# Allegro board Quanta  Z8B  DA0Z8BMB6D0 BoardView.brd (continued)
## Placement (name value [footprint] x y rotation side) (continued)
PC46  0.1u/50v_6  [CC0603]  39.43 65.7 90 top
PC47  0.1u/50v_6  [CC0603]  41.76 69.46 90 top
PC48  0.1u/50v_6  [CC0603]  39.2 71.49 180 top
PC49  *2.2n/50v_4  [CC0402]  123.26 11.11 0 bottom
PC50  2200p/50v_6  [CC0603]  197.11 130.14 0 top
PC51  4.7u/25v_8  [CC0805]  196.72 128.39 180 top
PC52  1u/10v_4  [CC0402]  186.59 124.94 270 bottom
PC53  0.1u/50v_6  [CC0603]  192.03 126.84 0 bottom
PC54  0.1u/50v_6  [CC0603]  179.99 124.07 0 top
PC55  330u/2.5v_6x4.2  [ECAP6_3X6_1-7_2]  180.44 121.86 90 bottom
PC56  2200p/50v_6  [CC0603]  180.85 127.07 90 top
PC57  10u/6.3v_6  [CC0603]  54.46 27.3 0 bottom
PC58  10u/6.3v_6  [CC0603]  54.48 25.98 0 bottom
PC59  0.22u/10v_4  [CC0402]  49.96 29.1 180 top
PC60  10u/6.3v_6  [CC0603]  54.48 27.3 180 top
PC61  1u/10v_4  [CC0402]  53.06 33.62 180 bottom
PC62  2200p/50v_4  [CC0402]  51.39 41.7 270 top
PC63  4.7u/25v_8  [CC0805]  50.3 40.18 90 bottom
PC64  0.1u/50v_6  [CC0603]  56.29 33.72 0 top
PC65  0.1u/50v_6  [CC0603]  61.04 28.8 180 bottom
PC66  330u/2.5v_6x4.2  [ECAP6_3X6_1-7_2]  62.23 33.09 270 bottom
PC67  *680p/50v_6  [CC0603]  57.81 39.44 90 top
PC68  0.1u/10v_4  [CC0402]  49.96 30.27 180 top
PC69  0.01u/25v_4  [CC0402]  49.96 32.61 180 top
PC70  1u/10v_4  [CC0402]  57.18 85.72 270 bottom
PC71  0.1u/50v_6  [CC0603]  53.04 78.15 0 top
PC72  2200p/50v_4  [CC0402]  52.76 78.22 0 bottom
PC73  10u/25v_8  [CC0805]  53.42 79.88 0 top
PC74  10u/25v_8  [CC0805]  53.44 79.9 0 bottom
PC75  33u/25v_6x4.5  [ECAP6_3X6_1-7_2]  47.53 79.14 0 bottom
PC76  ev@2200p/50v_6  [CC0603]  133.25 190.24 90 top
PC77  0.47u/10v_4  [CC0402]  42.68 99 0 bottom
PC78  1n/50v_4  [CC0402]  42.8 89.78 270 top
PC79  2.2u/10v_6  [CC0603]  44.15 95.24 90 top
PC80  0.1u/10v_4  [CC0402]  100.22 122.33 0 top
PC82  22u/6.3v_8  [CC0805]  73.05 84.78 0 top
PC83  22u/6.3v_8  [CC0805]  73.05 86.94 0 top
PC84  0.22u/25v_6  [CC0603]  51.49 86.05 180 top
PC85  3300p/50v_6  [CC0603]  56.52 77.01 0 bottom
PC86  *0.1u/25v_4  [CC0402]  39.2 89.35 0 bottom
PC87  0.15u/10v_4  [CC0402]  40.87 90.04 270 bottom
PC88  0.1u/10v_4  [CC0402]  47.38 99.23 0 top
PC89  *0.1u/25v_4  [CC0402]  39.2 90.52 0 bottom
PC90  *100p/50v_4  [CC0402]  40.9 97.83 270 bottom
PC91  *330p/50v_4  [CC0402]  37.34 97.45 0 bottom
PC92  4700p/25v_4  [CC0402]  43.95 89.78 270 top
PC93  330p/50v_4  [CC0402]  39.76 97.83 270 bottom
PC94  *0.01u/50v_4  [CC0402]  37.37 94.86 0 bottom
PC95  10u/6.3v_6  [CC0603]  163.84 142.85 180 bottom
PC96  0.1u/25v_6  [CC0603]  163.84 144.12 0 bottom
PC97  0.1u/50v_6  [CC0603]  160.89 136.16 180 bottom
PC98  0.1u/10v_4  [CC0402]  153.57 134.44 180 bottom
PC99  10u/6.3v_6  [CC0603]  153.32 131.64 0 bottom
PC100  10u/6.3v_6  [CC0603]  153.32 133.04 0 bottom
PC101  1000p/50v_4  [CC0402]  158.04 140.51 180 bottom
PC102  *100p/50v_4  [CC0402]  167.31 138.35 0 bottom
PC103  1500p/50v_4  [CC0402]  167.31 139.44 180 bottom
PC104  0.01u/25v_4  [CC0402]  165.61 136 180 bottom
PC105  *2200p/50v_4  [CC0402]  30.38 50.49 270 top
PC106  0.1u/50v_6  [CC0603]  52.99 105.35 270 top
PC107  0.1u/50v_6  [CC0603]  54.38 105.35 270 top
PC108  ev@0.1u/50v_6  [CC0603]  191.44 146.17 90 top
PC109  ev@4.7u/25v_8  [CC0805]  179.51 146.27 270 top
PC110  ev@4.7u/25v_8  [CC0805]  187.56 146.5 270 top
PC111  ev@33u/25v_6x4.5  [ECAP6_3X6_1-7_2]  183.42 150.31 180 bottom
PC112  ev@1u/10v_4  [CC0402]  184.94 143.71 180 bottom
PC113  *ev@0.01u/25v_4  [CC0402]  179.17 134.31 180 top
PC114  ev@0.22u/25v_6  [CC0603]  188.34 141.55 0 top
PC115  ev@2200p/50v_4  [CC0402]  174.22 146.37 270 top
PC116  ev@0.1u/10v_4  [CC0402]  172.87 167.33 0 bottom
PC117  ev@10u/6.3v_8  [CC0805]  178.34 170.5 270 bottom
PC118  ev@330u/2v_7343  [CC7343]  185.75 162.07 270 top
PC119  ev@1u/10v_4  [CC0402]  183.16 135.58 270 bottom
PC120  ev@1000p/50v_6  [CC0603]  188.75 158.72 90 top
PC121  *e@0.01u/25v_4  [CC0402]  184.3 135.58 270 bottom
PC122  ev@5600p/25v_4  [CC0402]  186.59 135.58 90 bottom
PC123  ev@4700p/25v_4  [CC0402]  179.48 139.01 0 top
PC124  ev@22p/50v_4  [CC0402]  179.48 139.01 0 bottom
PC125  ev@0.22u/25v_6  [CC0603]  180.6 141.52 180 top
PC126  ev@2200p/50v_4  [CC0402]  192.69 146.42 270 top
PC127  ev@0.1u/50v_6  [CC0603]  175.52 146.48 90 top
PC128  ev@4.7u/25v_8  [CC0805]  177.32 146.25 270 top
PC129  ev@4.7u/25v_8  [CC0805]  189.72 146.5 270 top
PC130  *ev@22p/50v_4  [CC0402]  179.99 137.36 90 bottom
PC131  ev@0.1u/10v_4  [CC0402]  172.87 166.06 0 bottom
PC132  ev@10u/6.3v_8  [CC0805]  176.18 170.5 270 bottom
PC133  ev@330u/2v_7343  [CC7343]  181.03 162.1 270 top
PC134  ev@330u/2.5v_6x4.2  [ECAP6_3X6_1-7_2]  183.19 161.66 0 bottom
PC135  ev@1000p/50v_6  [CC0603]  178.08 158.74 90 top
PC136  *ev@1u/10v_4  [CC0402]  191.8 134.82 270 top
PC137  ev@4.7u/25v_8  [CC0805]  135.03 190.32 270 top
PC138  ev@0.1u/50v_6  [CC0603]  129.14 189.73 0 top
PC139  *ev@1u/10v_4  [CC0402]  120.6 189.3 180 top
PC140  ev@1u/10v_4  [CC0402]  127.16 187.44 270 top
PC141  0.22u/25v_6  [CC0603]  54.31 94.73 180 top
PC142  0.1u/10v_4  [CC0402]  72.93 90.62 0 top
PC143  22u/6.3v_8  [CC0805]  73.05 89.1 0 top
PC144  10u/25v_8  [CC0805]  56.14 88.77 0 top
PC145  *ev@2.2n/50v_4  [CC0402]  131.5 137.51 180 top
PC146  *ev@1u/10v_4  [CC0402]  118.26 132.91 270 top
PC147  *ev@2.2n/50v_4  [CC0402]  155.86 137.74 270 top
PC148  *ev@1u/10v_4  [CC0402]  163.6 147.14 270 top
PC149  0.1u/50v_6  [CC0603]  55.73 87.01 0 top
PC150  22u/6.3v_8  [CC0805]  73.05 82.62 0 top
PC151  ev@0.1u/50v_6  [CC0603]  141.38 187.06 0 bottom
PC152  *ev@680p/50v_6  [CC0603]  130.18 185.39 270 bottom
PC153  ev@330u/2v_7343  [CC7343]  145.06 183.79 0 bottom
PC154  1u/6.3v_4  [CC0402]  50.35 94.9 180 bottom
PC155  1u/10v_4  [CC0402]  60.2 94.07 270 bottom
PC156  *0.1u/25v_4  [CC0402]  39.22 92.86 0 bottom
PC157  0.15u/10v_4  [CC0402]  40.95 92.14 90 bottom
PC158  *0.1u/25v_4  [CC0402]  39.22 91.69 0 bottom
PC159  10u/25v_8  [CC0805]  56.14 88.77 0 bottom
PC160  3300p/50v_6  [CC0603]  59.06 87.88 270 bottom
PC161  2200p/50v_4  [CC0402]  55.45 87.09 0 bottom
PC162  *330u/2v_7343  [CC7343]  65.26 72.11 180 bottom
PC163  *2.2n/50v_4  [CC0402]  133.26 10.33 90 bottom
PC164  ev@4.7u/25v_8  [CC0805]  137.06 190.32 270 top
PC165  ev@4.7u/25v_8  [CC0805]  139.09 190.32 270 top
PC166  1000p/50v_4  [CC0402]  169.7 190.06 180 bottom
PC167  0.1u/50v_6  [CC0603]  167.16 190.06 0 bottom
PC168  1000p/50v_4  [CC0402]  174.02 180.92 90 bottom
PC169  0.1u/50v_6  [CC0603]  172.88 180.66 90 bottom
PC170  *680p/50v_6  [CC0603]  49.69 96.16 180 top
PD1  sbr1045sp5-13  [POWER-6_5-1_84-3P]  195.48 183.58 180 top
PD2  p4smafj20a  [D-DO-214AC]  195.1 167.25 0 top
PD3  1n4148ws  [DSM]  182.25 179.6 0 top
PD4  rb500v-40  [DSM]  162.05 190.95 180 top
PD5  1ps302  [UMT_213-3-1_3]  42.93 66.19 90 top
PD6  1ps302  [UMT_213-3-1_3]  39.22 69.41 0 top
PD7  da2j10100l  [DSM]  37.97 108.78 180 top
PJ1  power conn  [20288-04XX-4P-L]  188.5 172.6 180 bottom
PJ2  50458-00801-v01  [BAT-C144PL-K08A9-L-8P-L]  183.5 193.83 0 bottom
PL1  6.8uh_7x7x3  [CHOKE-PCMC063T-3R3MN-SMT]  169.45 185.79 180 bottom
PL2  2.2uh_7x7x3  [CHOKE-PCMC063T-3R3MN-SMT]  55.15 71.57 180 bottom
PL3  6.8uh_7x7x3  [CHOKE-PCMC063T-3R3MN-SMT]  53.88 49.98 180 bottom
PL4  2.2uh_7x7x3  [CHOKE-PCMC063T-3R3MN-SMT]  180.75 128.95 180 bottom
PL5  hcb2012kf800t50_0805  [RC0805]  175.98 189.98 90 top
PL6  0.15uh_7x7x4  [CHOKE-PCMC063T-R82MN-4P-SMT]  62.97 82.57 0 bottom
PL7  1uh_7x7x3  [CHOKE-PCMC063T-3R3MN-SMT]  160.94 131.21 180 bottom
PL8  ev@0.24uh_7x7x3  [CHOKE-ETQP4LR36AFM]  190.3 161.26 90 bottom
PL9  ev@0.24uh_7x7x3  [CHOKE-ETQP4LR36AFM]  175.92 161.74 90 bottom
PL10  hcb2012kf800t50_0805  [RC0805]  178.13 189.98 90 top
PL11  ev@2.2uh_7x7x3  [CHOKE-PCMC063T-3R3MN-SMT]  135.56 183.63 0 bottom
PL12  0.15uh_7x7x4  [CHOKE-PCMC063T-R82MN-4P-SMT]  65.58 92.42 0 bottom
PL13  2.2uh_7x7x3  [CHOKE-PCMC063T-3R3MN-SMT]  61.34 40.23 0 bottom
PL14  hcb2012kf800t50_0805  [RC0805]  49.41 82.82 0 top
PL15  hcb2012kf800t50_0805  [RC0805]  49.41 80.79 0 top
PQ1  aon6413  [SO-8FL-5P-OA]  187.61 185.59 270 top
PQ2  aon6413  [SO-8FL-5P-OA]  176.05 184.85 0 top
PQ3  imd2at108  [IMD]  195.07 171.21 180 top
PQ4  2n7002k  [SOT23_213-3_3-2]  177.5 179.57 270 top
PQ5  aon7410  [WDFN5-3_05X3_05-65]  166.63 184.4 90 top
PQ6  2n7002dw  [SC70-2_1-65-6P]  154.38 182.31 0 bottom
PQ7  aon7410  [WDFN5-3_05X3_05-65]  166.63 189.1 90 top
PQ8  *2n7002k  [SOT23_213-3_3-2]  161.4 187.78 270 top
PQ9  2n7002k  [SOT23_213-3_3-2]  147.45 179.52 90 bottom
PQ10  aon7410  [WDFN5-3_05X3_05-65]  47.91 72.31 0 bottom
PQ11  aon7410  [WDFN5-3_05X3_05-65]  46.89 47.82 0 bottom
PQ12  aon7752  [WDFN5-3_05X3_05-65]  47.91 67.63 270 bottom
PQ13  aon7752  [WDFN5-3_05X3_05-65]  46.89 52.52 90 bottom
PQ14  aon7408  [WDFN5-3_05X3_05-65]  51.84 63.06 180 top
PQ15  aon7408  [WDFN5-3_05X3_05-65]  56.54 60.9 270 top
PQ16  ao3404  [SOT23_213-3_3-2]  60.99 45.92 180 bottom
PQ17  ao3404  [SOT23_213-3_3-2]  155.55 78.91 0 top
PQ18  dtc144eu  [UMT_213-3-1_3]  118.85 8.21 270 bottom
PQ19  2n7002k  [SOT23_213-3_3-2]  170.26 6.89 270 bottom
PQ20  2n7002k  [SOT23_213-3_3-2]  176.79 15.39 270 bottom
PQ21  2n7002k  [SOT23_213-3_3-2]  125.25 8.32 270 bottom
PQ22  aon7410  [WDFN5-3_05X3_05-65]  187.99 130.37 180 top
PQ23  aon7752  [WDFN5-3_05X3_05-65]  183.67 127.73 270 top
PQ24  aon7408  [WDFN5-3_05X3_05-65]  169.3 127.93 180 bottom
PQ25  ev@aon7752  [WDFN5-3_05X3_05-65]  130.53 186.3 90 top
PQ26  ev@aon7410  [WDFN5-3_05X3_05-65]  135.11 186.12 270 top
PQ27  ao3409  [SOT23_213-3_3-2]  48.8 106.11 180 top
PQ28  2n7002k  [SOT23_213-3_3-2]  34.06 58.11 270 top
PQ29  dtc144eu  [UMT_213-3-1_3]  45.87 111.32 90 top
PQ30  dtc144eu  [UMT_213-3-1_3]  26.82 53.79 270 top
PQ31  2n7002k  [SOT23_213-3_3-2]  34.06 53.92 270 top
PQ32  2n7002k  [SOT23_213-3_3-2]  30.25 58.11 270 top
PQ33  2n7002k  [SOT23_213-3_3-2]  30.25 53.92 270 top
PQ34  2n7002k  [SOT23_213-3_3-2]  57.2 106.11 180 top
PQ35  2n7002k  [SOT23_213-3_3-2]  42.45 111.58 180 top
PQ36  ev@aon6414al  [SO-8FL-5P-OA]  191.14 144.8 90 bottom
PQ37  ev@aon6752  [SO-8FL-5P-OA]  191.64 152.8 180 bottom
PQ38  ev@aon6414al  [SO-8FL-5P-OA]  176.18 145.36 90 bottom
PQ39  ev@aon6752  [SO-8FL-5P-OA]  175.03 153.36 0 bottom
PQ40  *ev@2n7002k  [SOT23_213-3_3-2]  189.13 135.45 0 top
PQ41  aon6970  [POWER-5X6-1_27-7P]  53.98 40.63 90 bottom
PQ42  ao3404  [SOT23_213-3_3-2]  171.48 15.33 270 bottom
PQ43  ev@aon7408  [WDFN5-3_05X3_05-65]  134.9 135.96 0 top
PQ44  ev@2n7002k  [SOT23_213-3_3-2]  128.42 134.31 270 top
PQ45  ev@pdtc143tt  [SOT23_213-3_3-2]  120.8 134.31 270 top
PQ46  ev@2n7002k  [SOT23_213-3_3-2]  124.61 134.31 270 top
PQ47  ev@ao3404  [SOT23_213-3_3-2]  168.15 144.77 180 bottom
PQ48  ev@pdtc143tt  [SOT23_213-3_3-2]  159.79 148.53 270 top
PQ49  ev@2n7002k  [SOT23_213-3_3-2]  155.98 145.1 270 top
PQ50  ev@2n7002k  [SOT23_213-3_3-2]  155.98 140.91 270 top
PQ51  dtc144eu  [UMT_213-3-1_3]  128.55 8.58 270 bottom
PQ52  2n7002k  [SOT23_213-3_3-2]  131.88 7.14 270 bottom
PQ53  2n7002k  [SOT23_213-3_3-2]  135.66 7.13 270 bottom
PR1  0.01/f_0612  [RC3216]  195.86 179.65 0 top
PR2  *short_4  [SHORT0402]  192.69 179.39 180 top
PR3  220k_4  [RC0402]  182.53 183.2 270 top
PR4  33k/f_4  [RC0402]  181.43 187.9 270 top
PR5  *short_4  [SHORT0402]  192.69 180.54 180 top
PR6  220k_4  [RC0402]  183.77 186.17 270 top
PR7  *short_4  [SHORT0402]  197.69 170.93 270 top
PR8  10k_4  [RC0402]  182.53 187.9 90 top
PR9  *short_6  [SHORT0603]  152.73 185.01 270 bottom
PR10  63.4k/f_4  [RC0402]  155.27 184.35 180 top
PR11  10k/f_4  [RC0402]  154.84 184.32 180 bottom
PR12  100k_4  [RC0402]  192.56 186.86 270 top
PR13  20_1206  [RC1206]  152.81 185.24 225 top
PR14  *10k_4  [RC0402]  150.98 183.61 0 bottom
PR15  100k_4  [RC0402]  191.42 186.86 270 top
PR16  *short_6  [SHORT0603]  163.86 188.54 90 bottom
PR17  *0_4  [RC0402]  150.98 184.78 180 bottom
PR18  *short_4  [SHORT0402]  150.95 185.92 0 bottom
PR19  *short_4  [SHORT0402]  154.84 185.49 0 bottom
PR20  0.01/f_0612  [RC3216]  175.92 185.62 270 bottom
PR21  *short_4  [SHORT0402]  154.84 186.66 0 bottom
PR22  *4.7_6  [RC0603]  169.57 187.01 270 top
PR23  *short_4  [SHORT0402]  175.15 182.57 90 bottom
PR24  *short_4  [SHORT0402]  176.33 182.57 90 bottom
PR25  10k_4  [RC0402]  192.18 188.54 180 top
PR26  10k_4  [RC0402]  158.17 181.81 90 top
PR27  ev@100k/f_4  [RC0402]  120.78 191.33 0 top
PR28  316k/f_4  [RC0402]  151.06 181.3 0 bottom
PR29  *ev@short_6  [SHORT0603]  128.73 191 0 top
PR30  100_4  [RC0402]  180.95 190.57 90 top
PR31  ev@78.7k/f_4  [RC0402]  120.58 190.32 180 top
PR32  *short_4  [SHORT0402]  119.66 188.23 0 top
PR33  *100k_4  [RC0402]  155.91 187.9 0 top
PR34  100k/f_4  [RC0402]  155.35 189.05 180 bottom
PR35  1m_4  [RC0402]  182.09 190.57 90 top
PR36  100k_4  [RC0402]  157.02 181.81 270 top
PR37  *short_4  [SHORT0402]  179.86 190.57 270 top
PR38  100_4  [RC0402]  186.64 190.57 90 top
PR39  100_4  [RC0402]  183.24 190.57 90 top
PR40  *100k_4  [RC0402]  147.48 176.78 180 bottom
PR41  ev@49.9k/f_4  [RC0402]  196.04 173.63 0 top
PR42  *0_4  [RC0402]  157.66 182.29 180 bottom
PR43  *short_6  [SHORT0603]  46.08 57.73 0 top
PR44  10k/f_4  [RC0402]  38.79 56.91 180 top
PR45  *short_4  [SHORT0402]  39.6 63.29 90 top
PR46  *short_4  [SHORT0402]  40.14 55.75 180 bottom
PR47  *100k/f_4  [RC0402]  40.14 55.75 180 top
PR48  1/f_6  [RC0603]  43.11 56.97 180 top
PR49  1/f_6  [RC0603]  43.13 62.81 0 top
PR50  15.4k/f_4  [RC0402]  38.18 60.52 0 top
PR51  *4.7_6  [RC0603]  52.5 50.56 270 top
PR52  6.81k/f_4  [RC0402]  38.18 58.08 180 top
PR53  *4.7_6  [RC0603]  53.77 70.91 90 top
PR54  10k/f_4  [RC0402]  38.18 60.52 0 bottom
PR55  10k/f_4  [RC0402]  38.18 59.35 0 top
PR56  *short_6  [SHORT0603]  40.8 63.85 270 top
PR57  107k/f_4  [RC0402]  38.18 61.69 180 bottom
PR58  52.3k/f_4  [RC0402]  38.08 58.08 180 bottom
PR59  *short_6  [SHORT0603]  38.46 59.33 0 bottom
PR60  22_8  [RC0805]  39.37 73.3 180 top
PR61  1m_6  [RC0603]  122.45 7.65 90 bottom
PR62  22_8  [RC0805]  173.23 6.87 90 bottom
PR63  22_8  [RC0805]  179.76 14.78 90 bottom
PR64  1m_6  [RC0603]  120.76 11.12 180 bottom
PR65  *1m_6  [RC0603]  121.8 9.77 180 bottom
PR66  1m_6  [RC0603]  121.05 7.65 90 bottom
PR67  100k/f_4  [RC0402]  191.95 119.78 90 bottom
PR68  *short_4  [SHORT0402]  189.1 119.78 270 top
PR69  *short_6  [SHORT0603]  194.08 125.95 90 bottom
PR70  93.1k/f_4  [RC0402]  190.91 119.78 270 bottom
PR71  *100k/f_4  [RC0402]  189.1 119.78 270 bottom
PR72  464k/f_4  [RC0402]  186.75 119.81 270 bottom
PR73  2.2_6  [RC0603]  180.85 129.86 90 top
PR74  5.1k/f_4  [RC0402]  187.91 119.78 270 top
PR75  10k/f_4  [RC0402]  187.96 119.78 90 bottom
PR76  100k/f_4  [RC0402]  58.07 28.26 90 top
PR77  *short_4  [SHORT0402]  57.84 28.39 270 bottom
PR78  *short_4  [SHORT0402]  59.08 28.39 270 bottom
PR79  2/f_6  [RC0603]  56.29 33.72 180 bottom
PR80  200k/f_4  [RC0402]  57.61 31.49 180 top
PR81  26.1k/f_4  [RC0402]  57.61 30.47 180 top
PR82  *4.7_6  [RC0603]  58.58 41.34 0 top
PR83  0_6  [RC0603]  51.36 27.12 270 top
PR84  10k/f_4  [RC0402]  49.46 30.96 270 bottom
PR85  *0_4  [RC0402]  57.18 31.08 90 bottom
PR86  30.1k/f_4  [RC0402]  49.96 31.44 180 top
PR87  ev@10k/f_4  [RC0402]  121.21 187.78 90 top
PR88  1_6  [RC0603]  51.16 96.11 180 bottom
PR89  64.9k/f_4  [RC0402]  47.73 87.47 270 bottom
PR90  274k/f_4  [RC0402]  46.54 87.65 270 bottom
PR91  *90.9k/f_4  [RC0402]  45.42 87.65 270 bottom
PR92  *39.2k/f_4  [RC0402]  40.82 87.6 270 bottom
PR93  100k/f_4_4250ntc  [RC0402]  59.29 78.22 180 bottom
PR94  20/f_6  [RC0603]  45.17 97.78 270 bottom
PR95  10k/f_4  [RC0402]  39.68 87.57 270 bottom
PR96  ev@464k/f_4  [RC0402]  119.66 187.9 180 bottom
PR97  ev@9.31k/f_4  [RC0402]  119.2 187.22 180 top
PR98  100k/f_4  [RC0402]  49.89 89.73 90 top
PR99  20k/f_4  [RC0402]  48.65 89.76 270 top
PR100  75k/f_4  [RC0402]  47.48 89.78 270 top
PR101  150k/f_4  [RC0402]  46.31 89.78 270 top
PR102  39k/f_4  [RC0402]  41.46 89.76 270 top
PR103  9.09k/f_4  [RC0402]  43.13 87.6 270 bottom
PR104  2.2_8  [RC0805]  57.26 79.42 90 bottom
PR105  2.2/f_6  [RC0603]  51.51 84.75 0 top
PR106  1.65k/f_4  [RC0402]  62.56 85.21 270 top
PR107  0_4  [RC0402]  63.7 85.21 270 top
PR108  2.32k/f_4  [RC0402]  65.27 87.84 180 bottom
PR109  *22.6k/f_4  [RC0402]  63.57 87.23 90 bottom
PR110  130/f_4  [RC0402]  50.96 97.4 0 bottom
PR111  *75/f_4  [RC0402]  48.02 98.79 90 bottom
PR112  56_4  [RC0402]  46.52 98.84 90 bottom
PR113  *56_4  [RC0402]  45.11 100.25 90 bottom
PR114  10k/f_4_3435kntc  [RC0402]  65.27 86.7 180 bottom
PR115  *short_4  [SHORT0402]  46.52 96.68 90 bottom
PR116  *short_4  [SHORT0402]  48.02 96.63 90 bottom
PR117  *short_4  [SHORT0402]  49.21 96.63 90 bottom
PR118  100k/f_4  [RC0402]  50.35 93.73 180 bottom
PR119  *100k/f_4  [RC0402]  49.28 91.48 180 top
PR120  *100k/f_4  [RC0402]  48.83 90.71 180 bottom
PR121  *ev@0_4  [RC0402]  189.38 139.26 0 top
PR122  *short_4  [SHORT0402]  49.41 95.07 0 top
PR123  *short_4  [SHORT0402]  40.4 95.09 180 bottom
PR124  *short_8  [SHORT0805]  48.37 92.99 180 top
PR125  *short_4  [SHORT0402]  40.39 96.21 180 bottom
PR126  2.2/f_6  [RC0603]  54.28 93.41 0 top
PR127  1.65k/f_4  [RC0402]  65.01 90.66 90 top
PR128  10k/f_4  [RC0402]  42.07 97.4 270 bottom
PR129  150k/f_4  [RC0402]  44.3 87.62 270 bottom
PR130  10_4  [RC0402]  37.37 98.62 0 bottom
PR131  *short_4  [SHORT0402]  48.04 87.67 180 top
PR132  10k/f_4  [RC0402]  40.44 99.56 0 bottom
PR133  39k/f_4  [RC0402]  45.14 89.78 270 top
PR134  10_4  [RC0402]  37.37 96.03 180 bottom
PR135  *short_4  [SHORT0402]  42.68 93.41 0 top
PR136  *short_4  [SHORT0402]  40.92 92.63 270 top
PR137  100k/f_4  [RC0402]  158.04 139.34 0 bottom
PR138  *short_6  [SHORT0603]  158.6 136.9 270 bottom
PR139  *short_4  [SHORT0402]  158.04 141.67 0 bottom
PR140  100k/f_4  [RC0402]  166.14 141.67 0 bottom
PR141  8.06k/f_4  [RC0402]  165.64 138.85 270 bottom
PR142  121k/f_4  [RC0402]  166.12 137.2 180 bottom
PR143  113k/f_4  [RC0402]  166.14 140.53 180 bottom
PR144  1m_6  [RC0603]  45.62 108.78 180 top
PR145  1m_4  [RC0402]  29.24 50.49 270 top
PR146  22_8  [RC0805]  34.19 50.62 0 top
PR147  22_8  [RC0805]  30.25 61.41 180 top
PR148  22_8  [RC0805]  34.19 61.41 180 top
PR149  1m_4  [RC0402]  31.52 50.49 270 top
PR150  1m_4  [RC0402]  28.09 50.49 90 top
PR151  *short_6  [SHORT0603]  51.59 106.37 270 top
PR152  *100k/f_6  [RC0603]  26.7 50.36 90 top
PR153  1.47k/f_4  [RC0402]  56.03 110.18 90 top
PR154  200k/f_4  [RC0402]  56.03 112.46 270 top
PR155  200k_6  [RC0603]  53.75 107.38 180 top
PR156  10k/f_4_3435ntc  [RC0402]  19.54 101.92 90 bottom
PR157  200k/f_4  [RC0402]  57.43 111.07 90 top
PR158  *short_6  [SHORT0603]  182.53 143.83 0 bottom
PR159  ev@12.4k/f_4  [RC0402]  182.04 134.99 90 top
PR160  ev@2.2/f_6  [RC0603]  188.55 141.24 0 bottom
PR161  ev@6.81k/f_4  [RC0402]  181.49 135.5 0 bottom
PR162  ev@100k/f_4  [RC0402]  191.67 139.26 0 bottom
PR163  *ev@1/f_4  [RC0402]  179.17 133.17 180 top
PR164  *short_4  [SHORT0402]  189.38 139.26 180 bottom
PR165  *ev@499k/f_4  [RC0402]  180.9 134.99 270 top
PR166  *short_4  [SHORT0402]  189.38 138.12 180 bottom
PR167  *short_4  [SHORT0402]  189.38 136.98 180 bottom
PR168  ev@2.2/f_6  [RC0603]  189.49 160.77 0 top
PR169  ev@10k_4  [RC0402]  179.48 140.15 0 top
PR170  ev@7.5k/f_4  [RC0402]  184.94 134.94 180 top
PR171  *short_4  [SHORT0402]  179.48 140.18 180 bottom
PR172  ev@27k/f_4  [RC0402]  185.45 135.58 90 bottom
PR173  ev@10k_4  [RC0402]  191.67 135.83 0 bottom
PR174  ev@0_4  [RC0402]  184.94 136.09 0 top
PR175  ev@2.2/f_6  [RC0603]  180.57 141.52 180 bottom
PR176  *ev@0_4  [RC0402]  191.67 138.12 180 bottom
PR177  ev@16k/f_6  [RC0603]  176.81 139.01 0 top
PR178  ev@6.2k/f_4  [RC0402]  183.14 135.58 90 top
PR179  *ev@5.1k/f_4  [RC0402]  186.59 135.58 90 top
PR180  *short_4  [SHORT0402]  178.84 137.36 90 bottom
PR181  *short_4  [SHORT0402]  179.35 135.58 0 bottom
PR182  ev@1.74k_4  [RC0402]  183.16 133.42 90 top
PR183  ev@2.2/f_6  [RC0603]  177.27 160.77 180 top
PR184  0_4  [RC0402]  66.18 90.63 90 top
PR185  *short_4  [SHORT0402]  176.94 137.86 180 bottom
PR186  *short_4  [SHORT0402]  176.94 136.72 0 bottom
PR187  *short_4  [SHORT0402]  176.94 135.58 0 bottom
PR188  *short_4  [SHORT0402]  176.94 134.44 0 bottom
PR189  *ev@10k_4  [RC0402]  191.67 136.98 0 bottom
PR190  *ev@4.7_6  [RC0603]  130.18 182.64 270 bottom
PR191  0_4  [RC0402]  151.03 179.84 0 bottom
PR192  2.49k/f_4  [RC0402]  43.29 97.38 90 bottom
PR193  *0_4  [RC0402]  50.37 92.58 180 bottom
PR194  2.2_8  [RC0805]  60.66 88.46 90 bottom
PR195  *0_4  [RC0402]  48.82 89.55 0 bottom
PR196  2.32k/f_4  [RC0402]  68.76 87.17 180 bottom
PR197  ev@1m_4  [RC0402]  117.12 135.2 270 top
PR198  ev@22_8  [RC0805]  131.47 134.56 270 top
PR199  ev@1m_4  [RC0402]  128.86 131.69 0 top
PR200  *short_4  [SHORT0402]  115.98 132.91 90 top
PR201  ev@1m_4  [RC0402]  118.26 135.2 90 top
PR202  ev@100k_4  [RC0402]  117.12 132.91 90 top
PR203  ev@1m_4  [RC0402]  163.6 149.42 270 top
PR204  ev@22_8  [RC0805]  155.48 148.91 90 top
PR205  ev@1m_4  [RC0402]  154.59 137.74 270 top
PR206  *short_4  [SHORT0402]  164.75 147.14 90 top
PR207  ev@1m_4  [RC0402]  162.46 149.42 90 top
PR208  ev@100k_4  [RC0402]  162.46 147.14 90 top
PR209  10_6  [RC0603]  158.37 190.47 90 bottom
PR210  7.5_6  [RC0603]  157.1 190.47 90 bottom
PR211  *22.6k/f_4  [RC0402]  67.06 87.72 270 bottom
PR212  10k/f_4_3435kntc  [RC0402]  68.76 88.33 180 bottom
PR213  1m_6  [RC0603]  128.5 11.16 0 bottom
PR214  1m_6  [RC0603]  125.71 11.14 0 bottom
PR215  *1m_6  [RC0603]  130.63 10.6 90 bottom
PR216  1m_6  [RC0603]  131.99 10.6 90 bottom
PR217  22_8  [RC0805]  135.68 10.28 0 bottom
PR218  *0_8  [RC0805]  45.98 95.7 270 top
PU1  bq24737rgrr  [PVQFN20-3_5X3_5-5-25P]  158.9 186.61 180 bottom
PU2  *ip4223-cz6  [SOT23-6-2_8-95-6P]  189.89 190.67 180 top
PU3  tps51225rukr  [QFN20-3X3-4-26P]  41.53 59.86 0 top
PU4  tps51211dscr  [SON10-3X3-5-16P]  189.64 123.79 180 bottom
PU5  tps51216rukr  [QFN20-3X3-4-26P]  54.26 30.8 90 bottom
PU6  csd97374cq4m  [SON8-4_5X3_5-5-9P-SMT]  54.05 83.41 270 bottom
PU7  tps51631arsmr  [QFN32-4X4-4-42P-1H]  44.81 92.63 180 bottom
PU8  tps54318rter  [QFN16-3X3-5-22P]  162.28 139.57 0 bottom
PU9  as393mtr-e1  [SOIC8-6-1_27]  51.34 110.94 90 top
PU10  ev@up1658rqkf  [QFN20-3X3-4-21P-0_8H]  184.53 139.77 270 bottom
PU11  ev@tps51211dscr  [SON10-3X3-5-16P]  124.21 189.58 270 top
PU12  csd97374cq4m  [SON8-4_5X3_5-5-9P-SMT]  56.85 92.25 270 bottom
Q1  ev@2n7002k  [SOT23_213-3_3-2]  158.07 178.35 180 top
Q2  *mmbt3904-7-f  [SOT23_213-3_3-2]  173.64 176.98 0 top
Q3  ev@2n7002dw  [SC70-2_1-65-6P]  154.4 172.24 0 top
Q4  *ev@ao3413  [SOT23_213-3_3-2]  159.67 170.6 0 top
Q5  *ev@2n7002k  [SOT23_213-3_3-2]  170.24 168.75 90 top
Q6  ev@dtc144eua  [UMT_213-3-1_3]  169.52 160.55 270 top
Q7  ev@metr3904-g  [SOT23_213-3_3-2]  166.22 160.29 270 top
Q8  2n7002dw  [SC70-2_1-65-6P]  110.01 158.57 0 top
Q9  dtc144eua  [UMT_213-3-1_3]  106.83 154.76 270 top
Q10  ev@2n7002k  [SOT23_213-3_3-2]  162.18 153.19 180 top
Q11  ev@dtc144eu  [UMT_213-3-1_3]  169.04 172.18 180 top
Q12  ev@mmbt3904-7-f  [SOT23_213-3_3-2]  160.61 167 180 top
Q13  2n7002  [SOT23_213-3_3-2]  149 120.43 90 top
Q14  2n7002_200ma  [SOT23_213-3_3-2]  182.55 114.83 180 top
Q15  *2n7002k  [SOT23_213-3_3-2]  179.41 110.96 0 top
Q16  ap2331sa-7  [SOT23_213-3_3-2]  16.41 108.15 180 top
Q17  *dtc144eua  [UMT_213-3-1_3]  23.96 108.83 90 top
Q18  2n7002k  [SOT23_213-3_3-2]  32.95 105.61 270 top
Q19  *ao6402a  [TSOP6-2_8-95]  194.18 99.38 270 top
Q20  dmn601k-7  [SOT23_213-3_3-2]  196.95 95.09 270 top
Q21  *2n7002dw  [SC70-2_1-65-6P]  192.97 94.76 0 top
Q22  2n7002  [SOT23_213-3_3-2]  183.26 92.59 270 top
Q23  2n7002  [SOT23_213-3_3-2]  187.07 92.59 270 top
Q24  *evg@2n7002k  [SOT23_213-3_3-2]  163.38 182.01 90 bottom
Q25  *2n7002  [SOT23_213-3_3-2]  182.57 87.45 90 top
Q26  *evg@2n7002k  [SOT23_213-3_3-2]  168.36 169.46 90 bottom
Q27  2n7002  [SOT23_213-3_3-2]  176.63 87.29 0 top
Q28  pdtc144eu  [UMT_213-3-1_3]  186.29 86.91 0 top
Q29  2n7002  [SOT23_213-3_3-2]  176.63 83.53 0 top
Q30  mmbt3904  [UMT_213-3-1_3]  173.28 79.22 0 top
Q31  *aon7410  [POWER-3_3X3_3-65-5P-SMT]  100.1 75.13 90 top
Q32  *2n7002  [SOT23_213-3_3-2]  96.42 73.86 90 top
Q33  *2n7002  [SOT23_213-3_3-2]  109.47 73.85 270 top
Q34  *2n7002  [SOT23_213-3_3-2]  81.82 70.4 180 top
Q35  ap2302gn  [SOT23_213-3_3-2]  126.52 69.79 90 top
Q36  ap2302gn  [SOT23_213-3_3-2]  130.3 69.79 90 top
Q37  2n7002k  [SOT23_213-3_3-2]  20.35 68.24 90 top
Q38  2n7002  [SOT23_213-3_3-2]  86.77 67.86 0 top
Q39  ap2302gn  [SOT23_213-3_3-2]  92.54 67.73 270 top
Q40  ap2331sa-7  [SOT23_213-3_3-2]  17.91 63.14 180 top
Q41  2n7002k  [SOT23_213-3_3-2]  23.27 61.03 0 top
Q42  2n7002e  [SOT23_213-3_3-2]  17.93 59.12 180 top
Q43  2n7002k  [SOT23_213-3_3-2]  23.27 57.22 0 top
Q44  2n7002dw  [SC70-2_1-65-6P]  24.07 26.12 90 top
Q45  ev@2n7002k  [SOT23_213-3_3-2]  169.27 176.93 180 bottom
Q46  2n7002  [SOT23_213-3_3-2]  119.73 126.74 90 bottom
Q47  *me2303t1  [SOT23_213-3_3-2]  181.41 114.72 0 bottom
Q48  *dtc144eua  [UMT_213-3-1_3]  185.68 114.52 0 bottom
Q49  *me2303t1  [SOT23_213-3_3-2]  189.54 113.1 270 bottom
Q50  dtc144eua  [UMT_213-3-1_3]  185.17 111.09 90 bottom
Q51  *kbl@dtc144eu  [UMT_213-3-1_3]  158.55 64.08 0 bottom
Q52  *kbl@ao3413  [SOT23_213-3_3-2]  154.85 62.26 270 bottom
Q53  2n7002k  [SOT23_213-3_3-2]  158.58 60.72 90 bottom
Q54  2n7002  [SOT23_213-3_3-2]  157.78 55.43 180 bottom
Q55  2n7002  [SOT23_213-3_3-2]  157.78 51.5 180 bottom
Q56  2n7002dw  [SC70-2_1-65-6P]  186.24 47.07 180 bottom
Q57  2n7002k  [SOT23_213-3_3-2]  19.36 30.02 90 bottom
Q58  2n7002dw  [SC70-2_1-65-6P]  21.49 112.97 0 top
Q59  *fdv301n  [SOT23_213-3_3-2]  179.91 173.69 0 top
Q60  mmbt3904-7-f  [SOT23_213-3_3-2]  175.75 173.04 90 top
R1  tsu@0_4  [RC0402]  109.96 187.39 180 top
R2  *10k_4  [RC0402]  171.48 179.52 0 top
R3  100k_4  [RC0402]  115.04 179.22 180 top
R4  *100k_4  [RC0402]  115.04 178.2 180 top
R5  ts@0_6  [RC0603]  117 176.07 0 top
R6  *short_6  [SHORT0603]  111.41 175.76 270 top
R7  *ev@4.99k/f_4  [RC0402]  149.66 174.03 90 top
R8  evg@0_8  [RC0805]  159.36 173.45 180 top
R9  ev@10k/f_4  [RC0402]  148.1 173.38 90 top
R10  ev@4.7k_4  [RC0402]  151.16 171.9 270 top
R11  *ev@200k_4  [RC0402]  162.94 171.7 0 top
R12  ev@4.7k_4  [RC0402]  152.83 170.45 180 top
R13  ev@1.33k/f_4  [RC0402]  114.45 169.87 90 top
R14  ev@51.1/f_4  [RC0402]  138.03 169.84 90 top
R15  ev@10k_4  [RC0402]  148.7 169.59 270 top
R16  *ev@60.4_4  [RC0402]  135.06 169.21 90 top
R17  *short_8  [SHORT0805]  104.87 168.39 90 top
R18  ev@1.33k/f_4  [RC0402]  113.95 168.09 0 top
R19  ev@42.2/f_4  [RC0402]  136.86 167.94 180 top
R20  ev@40.2/f_4  [RC0402]  138.76 167.3 270 top
R21  ev@10k/f_4  [RC0402]  113.95 166.82 180 top
R22  ev@243/f_4  [RC0402]  128.27 166.62 0 top
R23  ev@100k/f_4  [RC0402]  169.85 165.04 180 top
R24  ev@4.7k_4  [RC0402]  169.57 163.14 0 top
R25  ev@10k/f_4  [RC0402]  113.95 161.74 0 top
R26  *short_4  [SHORT0402]  105.97 161.36 90 top
R27  100k_4  [RC0402]  107.09 161.36 270 top
R28  *short_4  [SHORT0402]  108.41 160.95 270 top
R29  *ev@60.4_4  [RC0402]  140.48 160.83 270 top
R30  10k_4  [RC0402]  110.64 160.47 0 top
R31  *short_4  [SHORT0402]  106.58 159.58 0 top
R32  100k_4  [RC0402]  106.58 158.57 180 top
R33  ev@4.7k_4  [RC0402]  163.12 157.55 0 top
R34  10k_4  [RC0402]  106.58 157.3 0 top
R35  ev@4.7k_4  [RC0402]  169.11 157.02 180 top
R36  ev@10k/f_4  [RC0402]  162.1 155.74 0 top
R37  ev@1.33k/f_4  [RC0402]  113.95 154.78 180 top
R38  *100k_4  [RC0402]  110.9 154.12 90 top
R39  *ev@0_4  [RC0402]  164.92 153.59 90 top
R40  ev@1.33k/f_4  [RC0402]  113.44 153.1 270 top
R41  ev@243/f_4  [RC0402]  113.95 151.33 180 top
R42  ev@10k/f_4  [RC0402]  113.28 150.06 0 top
R43  ev@160/f_4  [RC0402]  114.19 148.28 90 top
R44  *short_4  [SHORT0402]  153.19 143.58 90 top
R45  ev@0_4  [RC0402]  137.95 140.28 180 top
R46  49.9/f_4  [RC0402]  118.06 127.88 90 top
R47  2.2k_4  [RC0402]  149.46 124.76 180 top
R48  2.2k_4  [RC0402]  149.46 123.59 180 top
R49  1m_4  [RC0402]  152.1 122.42 180 top
R50  *short_4  [SHORT0402]  96.1 122.32 90 top
R51  1k_4  [RC0402]  97.38 122.32 90 top
R52  100k_4  [RC0402]  146.31 121.06 270 top
R53  *short_8  [SHORT0805]  164.92 120.67 0 top
R54  *short_8  [SHORT0805]  167.7 121.35 90 top
R55  *short_6  [SHORT0603]  171.3 120.36 270 top
R56  51_4  [RC0402]  97.4 120.09 90 top
R57  51_4  [RC0402]  98.54 120.09 90 top
R58  10k_4  [RC0402]  99.69 120.09 270 top
R59  *short_4  [SHORT0402]  96.17 120.08 270 top
R60  *1/f_4  [RC0402]  160.94 117.77 180 top
R61  *short_8  [SHORT0805]  153.27 117.62 270 top
R62  *short_8  [SHORT0805]  162.97 117.05 90 top
R63  1m_4  [RC0402]  23.35 69.61 0 top
R64  *short_8  [SHORT0805]  165.21 117.12 90 top
R65  *10k_4  [RC0402]  134.63 116.06 180 top
R66  *short_4  [SHORT0402]  158.73 115.31 0 top
R67  *short_6  [SHORT0603]  167.04 115.22 270 top
R68  *10k_4  [RC0402]  134.63 114.89 180 top
R69  22_4  [RC0402]  172.88 114.84 90 top
R70  *short_6  [SHORT0603]  164.88 114.58 180 top
R71  51_4  [RC0402]  91.52 114.57 180 top
R72  *0_6  [RC0603]  179.79 114.34 270 top
R73  *short_6  [SHORT0603]  168.31 114.2 90 top
R74  *short_6  [SHORT0603]  169.58 114.2 270 top
R75  *short_8  [SHORT0805]  151.24 113.95 90 top
R76  *short_6  [SHORT0603]  176.51 113.91 0 top
R77  *10k_4  [RC0402]  171.74 113.82 90 top
R78  *short_6  [SHORT0603]  155.88 113.68 90 top
R79  *7.5k/f_4  [RC0402]  157.89 113.57 270 top
R80  7.5k/f_4  [RC0402]  158.91 113.57 270 top
R81  649/f_4  [RC0402]  166.02 113.31 0 top
R82  ev@4.7k_4  [RC0402]  166.02 168.98 180 top
R83  *ev@100k/f_4  [RC0402]  169.19 174.11 180 top
R84  ev@4.7k_4  [RC0402]  169.19 175.25 0 top
R85  ev@4.7k_4  [RC0402]  156.95 167.53 90 top
R86  22_4  [RC0402]  173.08 112.79 90 top
R87  *short_4  [SHORT0402]  135.99 111.85 270 top
R88  *short_4  [SHORT0402]  134.72 111.84 270 top
R89  150_4  [RC0402]  133.52 111.84 270 top
R90  *10k_4  [RC0402]  132.26 111.82 90 top
R91  1m_4  [RC0402]  182.02 111.48 90 top
R92  33_4  [RC0402]  184.51 111.47 270 top
R93  10k_4  [RC0402]  172.32 110.97 0 top
R94  *0_4  [RC0402]  196.12 110.69 180 top
R95  *short_6  [SHORT0603]  154.51 110.25 180 top
R96  10k_4  [RC0402]  170.67 109.77 0 top
R97  *short_4  [SHORT0402]  196.12 109.42 180 top
R98  *short_6  [SHORT0603]  173.07 109.4 180 top
R99  *short_6  [SHORT0603]  175.38 108.85 270 top
R100  24.9/f_4  [RC0402]  130.76 108.91 225 top
R101  *short_8  [SHORT0805]  147.25 108.53 0 top
R102  0_4  [RC0402]  178.55 108.24 0 top
R103  *short_4  [SHORT0402]  88.91 108.21 0 top
R104  10k_4  [RC0402]  196.12 108.15 0 top
R105  0.002/f_1206  [RC1206]  136.14 108.03 0 top
R106  8.2k_4  [RC0402]  182.19 107.89 0 top
R107  24.9/f_4  [RC0402]  132.34 107.77 90 top
R108  *short_6  [SHORT0603]  176.94 107.43 270 top
R109  8.2k_4  [RC0402]  179.15 107.05 0 top
R110  *short_4  [SHORT0402]  88.92 107.03 180 top
R111  8.2k_4  [RC0402]  182.16 106.72 0 top
R112  20k_4  [RC0402]  85.9 106.25 270 top
R113  1k_4  [RC0402]  87.11 106.25 90 top
R114  *short_6  [SHORT0603]  172.62 106.16 180 top
R115  *1k_4  [RC0402]  88.92 105.85 180 top
R116  *short_6  [SHORT0603]  141.36 105.73 90 top
R117  *0.002/f_1206  [RC1206]  136.14 105.59 0 top
R118  *short_4  [SHORT0402]  22.66 104.84 180 top
R119  1k_4  [RC0402]  24.74 104.84 180 top
R120  15k_4  [RC0402]  26.85 105.35 180 top
R121  8.2k_4  [RC0402]  182.19 105.33 0 top
R122  22.6/f_4  [RC0402]  169.96 105.19 180 top
R123  *short_4  [SHORT0402]  88.92 104.69 0 top
R124  *43/j_4  [RC0402]  86.68 104.56 180 top
R125  *10k/j_4  [RC0402]  22.66 103.7 180 top
R126  49.9/f_4  [RC0402]  117.62 104.1 270 top
R127  *short_6  [SHORT0603]  182.55 103.95 0 top
R128  0.002/f_1206  [RC1206]  178.09 103.79 0 top
R129  *short_6  [SHORT0603]  148.19 103.6 180 top
R130  *0/j_4  [RC0402]  35.49 103.57 270 top
R131  *1k_4  [RC0402]  88.93 103.47 0 top
R132  *short_4  [SHORT0402]  86.69 103.38 180 top
R133  10k/j_4  [RC0402]  33.33 103.07 180 top
R134  *short_8  [SHORT0805]  194.27 102.48 0 top
R135  *1k_4  [RC0402]  88.97 102.23 0 top
R136  *0_6  [RC0603]  178.92 101.97 0 top
R137  10k_4  [RC0402]  197.49 101.8 90 top
R138  7.5k/f_4  [RC0402]  153.78 101.13 90 top
R139  *0_6  [RC0603]  175.39 101.11 0 top
R140  1k_4  [RC0402]  88.89 101.04 0 top
R141  *short_4  [SHORT0402]  86.68 100.87 180 top
R142  *short_8  [SHORT0805]  151.54 100.65 180 top
R143  *short_6  [SHORT0603]  178.73 100.68 0 top
R144  *short_6  [SHORT0603]  170.97 100.48 0 top
R145  0.002/f_2512  [RC2512]  141.69 100.4 270 top
R146  *1k_4  [RC0402]  175.4 99.85 180 top
R147  *1k_4  [RC0402]  88.28 99.69 0 top
R148  *short_4  [SHORT0402]  86.07 99.64 180 top
R149  *short_6  [SHORT0603]  178.81 99.21 0 top
R150  22_8  [RC0805]  197.05 98.88 90 top
R151  *0_6  [RC0603]  176.07 98.44 0 top
R152  *short_4  [SHORT0402]  87.43 98.42 180 top
R153  100_4  [RC0402]  153.22 98.35 180 top
R154  *10k_4  [RC0402]  189.21 98.3 270 top
R155  *1k_4  [RC0402]  162.06 97.92 90 top
R156  *1k_4  [RC0402]  123.72 97.57 0 top
R157  *0_4  [RC0402]  153.22 97.34 180 top
R158  1m_4  [RC0402]  177.24 97.15 0 top
R159  *100k  [RC0402]  193.73 96.77 0 top
R160  8.2k_4  [RC0402]  179.76 96.39 180 top
R161  7.5k/f_4  [RC0402]  152.87 96.32 180 top
R162  1k_4  [RC0402]  151 96.26 90 top
R163  *short_4  [SHORT0402]  188.23 96.07 90 top
R164  2.49k/f_4  [RC0402]  23.8 95.57 180 top
R165  *short_4  [SHORT0402]  167.42 95.52 90 top
R166  0_4  [RC0402]  152.74 95.3 0 top
R167  *1k_4  [RC0402]  158.02 95.15 0 top
R168  *100k_4  [RC0402]  170.21 95.15 90 top
R169  10k_4  [RC0402]  181.93 95.11 0 top
R170  *1k_4  [RC0402]  123.79 95.02 0 top
R171  390k/f_4  [RC0402]  176.58 94.97 180 top
R172  10k_4  [RC0402]  168.56 94.52 270 top
R173  20k/f_4  [RC0402]  176.18 93.9 0 top
R174  10k_4  [RC0402]  171.74 93.88 180 top
R175  *0_4  [RC0402]  152.69 93.76 0 top
R176  10k_4  [RC0402]  154.85 93.76 0 top
R177  *100k  [RC0402]  193.73 92.88 180 top
R178  10k_4  [RC0402]  152.69 92.61 0 top
R179  10k_4  [RC0402]  154.85 92.61 0 top
R180  2.2k_4  [RC0402]  178.26 92.5 90 top
R181  *0_6  [RC0603]  161.35 92.5 270 top
R182  *100k  [RC0402]  196.32 92.42 0 top
R183  20k/f_4  [RC0402]  175.36 92.38 0 top
R184  10k_4  [RC0402]  163.67 92.32 90 top
R185  10k_4  [RC0402]  165.26 92.23 90 top
R186  499/f_4  [RC0402]  166.28 92.23 270 top
R187  499/f_4  [RC0402]  167.42 92.23 270 top
R188  10k_4  [RC0402]  168.56 92.23 270 top
R189  10k_4  [RC0402]  169.71 92.23 90 top
R190  *short_8  [SHORT0805]  159.06 92.05 0 top
R191  *short_4  [SHORT0402]  114.91 91.31 0 top
R192  *short_4  [SHORT0402]  111.9 91.09 0 top
R193  *0_4  [RC0402]  189.56 91.05 270 top
R194  *0_4  [RC0402]  195.59 90.74 90 top
R195  *short_4  [SHORT0402]  196.86 90.74 90 top
R196  2.2k_4  [RC0402]  178.26 90.41 270 top
R197  *10k_4  [RC0402]  179.51 90.02 270 top
R198  4.7k_4  [RC0402]  186.67 90.01 0 top
R199  4.7k_4  [RC0402]  183.53 90.01 0 top
R200  *short_4  [SHORT0402]  171.25 89.96 90 top
R201  *10k_4  [RC0402]  159.42 89.87 90 top
R202  *short_4  [SHORT0402]  167.93 89.84 90 top
R203  10k_4  [RC0402]  169.07 89.84 90 top
R204  *0_4  [RC0402]  151.54 89.82 90 top
R205  10k_4  [RC0402]  152.56 89.82 90 top
R206  10k_4  [RC0402]  153.7 89.82 270 top
R207  10k_4  [RC0402]  154.85 89.82 90 top
R208  8.2k_4  [RC0402]  155.99 89.82 270 top
R209  *1k_4  [RC0402]  157.13 89.82 90 top
R210  5.11/f_4  [RC0402]  161.7 89.82 270 top
R211  *short_4  [SHORT0402]  162.85 89.82 90 top
R212  *short_4  [SHORT0402]  163.99 89.82 270 top
R213  *short_4  [SHORT0402]  165.13 89.82 270 top
R214  10k_4  [RC0402]  166.66 89.82 90 top
R215  *short_4  [SHORT0402]  158.27 89.81 90 top
R216  *0_4  [RC0402]  188.74 89.36 180 top
R217  10k_4  [RC0402]  186.66 88.82 180 top
R218  *short_4  [SHORT0402]  179.77 87.89 270 top
R219  210/f_4  [RC0402]  161.38 87.78 90 top
R220  10k_4  [RC0402]  157.91 87.72 0 top
R221  *1k_4  [RC0402]  163.98 87.42 90 top
R222  *1k_4  [RC0402]  165.13 87.41 90 top
R223  10k_4  [RC0402]  159.52 87.33 270 top
R224  2.2k_4  [RC0402]  173.85 87.2 90 top
R225  *0/j_6  [RC0603]  11.56 86.12 180 top
R226  *10k_4  [RC0402]  156.75 85.12 90 top
R227  10k_4  [RC0402]  157.89 85.12 90 top
R228  *short_4  [SHORT0402]  159.04 85.12 90 top
R229  *0_4  [RC0402]  160.18 85.12 270 top
R230  2.2k_4  [RC0402]  173.85 84.92 270 top
R231  *0_4  [RC0402]  187.12 84.9 0 top
R232  *0_4  [RC0402]  182.83 84.87 180 top
R233  75/f_12  [RC1206]  25.17 84.1 180 top
R234  *short_4  [SHORT0402]  185.3 83.28 90 top
R235  *0_4  [RC0402]  181.32 81.82 90 top
R236  75/f_12  [RC1206]  25.17 81.64 180 top
R237  75/f_12  [RC1206]  25.17 78.81 180 top
R238  *tpm@4.7k  [RC0402]  182.43 78.01 0 top
R239  *short_4  [SHORT0402]  178.97 77.67 90 top
R240  *tpmi@0_4  [RC0402]  180.24 77.67 90 top
R241  68.1k/f_4  [RC0402]  174.37 77.29 0 top
R242  4.7k_4  [RC0402]  167.77 77.27 180 top
R243  4.7k_4  [RC0402]  169.97 77.26 180 top
R244  150k/f_4  [RC0402]  172.18 77.26 0 top
R245  *220_8  [RC0805]  109.49 76.96 180 top
R246  *1k/f_4  [RC0402]  94.96 76.51 0 top
R247  *tpmi@4.7k  [RC0402]  182.7 76.41 90 top
R248  75/f_12  [RC1206]  25.17 76.4 180 top
R249  *tpm@10k_4  [RC0402]  181.51 76.4 90 top
R250  *tpm@0_4  [RC0402]  183.92 76.38 90 top
R251  100/f_4  [RC0402]  91.95 75.86 90 top
R252  100/f_4  [RC0402]  90.73 74.72 90 top
R253  75/f_4  [RC0402]  89.51 74.14 90 top
R254  *1k/f_4  [RC0402]  93.27 74.06 0 top
R255  1.8k/f_4  [RC0402]  83.21 73.65 90 top
R256  *short_4  [SHORT0402]  84.48 73.65 90 top
R257  *short_4  [SHORT0402]  77.11 73.34 180 top
R258  3.32k/f_4  [RC0402]  81.03 72.84 0 top
R259  tpmn@0_4  [RC0402]  188.51 72.81 0 top
R260  4.99k/f_4  [RC0402]  87.4 71.8 180 top
R261  *1k_4  [RC0402]  93.27 71.67 0 top
R262  *tpmi@0_4  [RC0402]  188.51 71.54 0 top
R263  *0_6  [RC0603]  95.91 71.06 0 top
R264  *39_4  [RC0402]  84.41 70.81 270 top
R265  *200/f_4  [RC0402]  75.25 70.7 90 top
R266  *0_4  [RC0402]  87.4 70.53 180 top
R267  *0_6  [RC0603]  92.99 70.53 0 top
R268  *0_6  [RC0603]  123.85 70.43 90 top
R269  *0_6  [RC0603]  132.95 70.4 90 top
R270  *20k/f_4  [RC0402]  188.5 70.32 180 top
R271  *tpmn@0_4  [RC0402]  175.87 69.61 0 top
R272  *0/j_6  [RC0603]  17.05 69.46 180 top
R273  *short_4  [SHORT0402]  188.51 69 180 top
R274  *short_4  [SHORT0402]  164.8 68.83 90 top
R275  43_4  [RC0402]  170.51 68.42 0 top
R276  10k_4  [RC0402]  166.5 68.34 180 top
R277  *short_4  [SHORT0402]  77.78 67.58 0 top
R278  1k_4  [RC0402]  82.83 67.23 270 top
R279  1k_4  [RC0402]  84.1 67.23 90 top
R280  *short_4  [SHORT0402]  17.05 66.74 180 top
R281  *0_4  [RC0402]  166.02 65.98 270 top
R282  100k_4  [RC0402]  169.87 65.78 270 top
R283  2.2k_4  [RC0402]  6.08 12.18 270 top
R284  20k_4  [RC0402]  17.05 65.6 0 top
R285  *0_6  [RC0603]  73.74 65.22 90 top
R286  *short_6  [SHORT0603]  75.13 65.22 270 top
R287  1k/f_4  [RC0402]  72.34 64.97 90 top
R288  1k_4  [RC0402]  79.78 64.94 90 top
R289  *0_4  [RC0402]  81.05 64.94 90 top
R290  *0_4  [RC0402]  82.32 64.94 90 top
R291  *10k_4  [RC0402]  184.82 64.52 90 top
R292  *short_6  [SHORT0603]  75.4 63.07 180 top
R293  1k/f_4  [RC0402]  72.85 62.71 90 top
R294  2.2k_4  [RC0402]  20.73 60.52 270 top
R295  2.2_6  [RC0603]  162.76 58.6 180 top
R296  *100k/f_4  [RC0402]  15.32 58.59 270 top
R297  10k_4  [RC0402]  136.46 57.91 90 top
R298  2.2k_4  [RC0402]  20.6 56.84 90 top
R299  *short_4  [SHORT0402]  14.27 56.53 180 top
R300  10k_4  [RC0402]  185.64 55.88 180 top
R301  *short_4  [SHORT0402]  14.27 55.51 180 top
R302  10k_4  [RC0402]  136.46 55.25 90 top
R303  *22_4  [RC0402]  162.02 55.06 180 top
R304  100k_4  [RC0402]  185.61 54.66 180 top
R305  470_4  [RC0402]  17.76 54.24 180 top
R306  *120/f_4  [RC0402]  16.16 53.66 270 top
R307  470_4  [RC0402]  17.76 53.09 180 top
R308  ev@10k_4  [RC0402]  161.78 52.73 0 top
R309  *short_6  [SHORT0603]  74.12 52.22 180 top
R310  470_4  [RC0402]  17.76 51.82 180 top
R311  *120/f_4  [RC0402]  16.16 51.25 270 top
R312  *short_6  [SHORT0603]  74.08 50.9 180 top
R313  *0_6  [RC0603]  71.33 50.89 180 top
R314  470_4  [RC0402]  17.76 50.68 180 top
R315  10k_4  [RC0402]  160.96 50.69 180 top
R316  470_4  [RC0402]  18.14 49.54 180 top
R317  100k_4  [RC0402]  158.91 49.09 270 top
R318  1k/f_4  [RC0402]  70.95 49.1 270 top
R319  1k/f_4  [RC0402]  72.09 49.1 270 top
R320  *120/f_4  [RC0402]  16.54 48.96 270 top
R321  470_4  [RC0402]  18.14 48.39 180 top
R322  2.2_6  [RC0603]  163.56 48.11 180 top
R323  10k_4  [RC0402]  135.19 47.12 270 top
R324  *ev@10k_4  [RC0402]  164.92 172.2 90 top
R325  10k_4  [RC0402]  136.33 47.12 270 top
R326  1k_4  [RC0402]  168.12 45.1 180 top
R327  *short_8  [SHORT0805]  188.3 41.6 90 top
R328  *short_4  [SHORT0402]  19.08 38.93 180 top
R329  100k_4  [RC0402]  161.78 53.78 180 top
R330  4.7k_4  [RC0402]  173.34 67.79 270 top
R331  4.7k_4  [RC0402]  174.48 67.79 270 top
R332  4.7k_4  [RC0402]  177.97 65.73 270 top
R333  *10k_4  [RC0402]  134.43 38.74 90 top
R334  10k_4  [RC0402]  135.57 38.74 90 top
R335  *short_6  [SHORT0603]  92.68 38.46 180 top
R336  *short_4  [SHORT0402]  19.08 37.92 180 top
R337  *0_6  [RC0603]  92.68 37.19 0 top
R338  47k_4  [RC0402]  25.81 36.9 270 top
R339  *short_4  [SHORT0402]  19.08 36.65 180 top
R340  4.7k_4  [RC0402]  176.57 65.73 270 top
R341  *10k_4  [RC0402]  185.4 62.91 180 top
R342  10k_4  [RC0402]  93.15 35.94 180 top
R343  10k_4  [RC0402]  95.18 35.94 180 top
R344  *short_4  [SHORT0402]  19.08 35.63 180 top
R345  33_4  [RC0402]  29.24 34.61 90 top
R346  *1k_4  [RC0402]  35.7 34.53 180 top
R347  *short_4  [SHORT0402]  19.08 34.23 180 top
R348  *10k_4  [RC0402]  36.25 33.41 0 top
R349  *short_4  [SHORT0402]  19.08 33.22 180 top
R350  *short_4  [SHORT0402]  24.62 32.71 90 top
R351  *100k_4  [RC0402]  19.2 31.95 180 top
R352  39.2k/f_4  [RC0402]  24.54 31.18 0 top
R353  20k/f_4  [RC0402]  24.54 30.17 0 top
R354  *short_4  [SHORT0402]  36.54 27.84 180 top
R355  2.2k_4  [RC0402]  18.7 27.12 0 top
R356  *short_4  [SHORT0402]  39.91 25.47 0 top
R357  4.7k_4  [RC0402]  20.83 24.76 180 top
R358  56_4  [RC0402]  18.6 24.71 0 top
R359  *short_4  [SHORT0402]  34.83 24.2 180 top
R360  *1k_4  [RC0402]  22.19 23.63 180 top
R361  *0_4  [RC0402]  39.91 23.18 0 top
R362  100k_4  [RC0402]  29.02 22.97 270 top
R363  *short_4  [SHORT0402]  22.13 21.53 270 top
R364  *short_4  [SHORT0402]  35.46 21.53 270 top
R365  *gs@0_6  [RC0603]  113.06 15.97 180 top
R366  *gs@4.7k_4  [RC0402]  108.33 14.57 180 top
R367  *gs@0_4  [RC0402]  108.33 13.43 180 top
R368  4.7k_4  [RC0402]  13.45 12.67 180 top
R369  56_4  [RC0402]  8.87 11.47 0 top
R370  *1k_4  [RC0402]  15.42 10.99 90 top
R371  *short_6  [SHORT0603]  103.81 9.92 270 top
R372  *short_6  [SHORT0603]  105.13 9.92 270 top
R373  *short_6  [SHORT0603]  106.46 9.92 270 top
R374  *short_6  [SHORT0603]  107.78 9.9 270 top
R375  *short_4  [SHORT0402]  16.75 9.02 270 top
R376  *gs@0_4  [RC0402]  111.79 8.83 270 top
R377  *gs@4.7k_4  [RC0402]  112.93 8.83 90 top
R378  *gs@0_4  [RC0402]  114.07 8.83 270 top
R379  *short_4  [SHORT0402]  115.98 185.49 180 bottom
R380  *short_4  [SHORT0402]  115.98 184.47 180 bottom
R381  *short_4  [SHORT0402]  115.98 183.2 180 bottom
R382  *short_4  [SHORT0402]  115.98 182.19 180 bottom
R383  *evg@0_4  [RC0402]  165.19 179.56 180 bottom
R384  ev@10k/f_4  [RC0402]  163.09 178.71 270 bottom
R385  *100k_4  [RC0402]  114.94 178.71 180 bottom
R386  *ev@4.99k/f_4  [RC0402]  150.32 178.45 0 bottom
R387  *ev@0_4  [RC0402]  165.15 178.12 0 bottom
R388  ev@2.2k_4  [RC0402]  159.35 177.51 90 bottom
R389  ev@2.2k_4  [RC0402]  157.04 177.49 90 bottom
R390  ev@10k/f_4  [RC0402]  155.91 177.49 90 bottom
R391  ev@2.2k_4  [RC0402]  158.19 177.49 90 bottom
R392  100k_4  [RC0402]  114.96 177.46 180 bottom
R393  ev@10k/f_4  [RC0402]  149.66 177.04 180 bottom
R394  *ev@10k/f_4  [RC0402]  149.66 176.02 180 bottom
R395  ev@10k/f_4  [RC0402]  157.05 175.31 270 bottom
R396  ev@2.2k_4  [RC0402]  155.93 175.28 270 bottom
R397  ev@2.2k_4  [RC0402]  159.45 175.25 270 bottom
R398  ev@2.2k_4  [RC0402]  158.21 175.25 270 bottom
R399  ev@10k/f_4  [RC0402]  160.66 175.23 270 bottom
R400  ev@10k/f_4  [RC0402]  149.66 175 180 bottom
R401  *ev@0_4  [RC0402]  162.5 174.79 180 bottom
R402  ev@10k/f_4  [RC0402]  168.79 174.26 0 bottom
R403  ev@10k/f_4  [RC0402]  163.07 172.99 90 bottom
R404  *ev@0_4  [RC0402]  168.84 172.38 180 bottom
R405  *evg@10k/f_4  [RC0402]  163.58 171.32 0 bottom
R406  *ev@10k_4  [RC0402]  163.58 169.92 0 bottom
R407  *ev@10k/f_4  [RC0402]  163.58 168.9 180 bottom
R408  *ev@10k/f_4  [RC0402]  163.58 167.79 180 bottom
R409  ev@160/f_4  [RC0402]  114.45 167.58 270 bottom
R410  evg@10k/f_4  [RC0402]  163.58 166.3 0 bottom
R411  *ev@10k/f_4  [RC0402]  165.76 166.01 180 bottom
R412  *short_4  [SHORT0402]  169.88 165.96 0 bottom
R413  ev@10k/f_4  [RC0402]  113.95 165.55 180 bottom
R414  *ev@0_4  [RC0402]  168 165.47 90 bottom
R415  ev@10k/f_4  [RC0402]  163.6 165.23 180 bottom
R416  *short_6  [SHORT0603]  110.39 165.17 90 bottom
R417  *short_6  [SHORT0603]  111.79 165.17 90 bottom
R418  *ev@10k/f_4  [RC0402]  165.79 164.88 180 bottom
R419  ev@243/f_4  [RC0402]  113.95 164.28 180 bottom
R420  ev@10k/f_4  [RC0402]  163.58 164.04 180 bottom
R421  *ev@10k/f_4  [RC0402]  165.76 163.79 180 bottom
R422  *ev@10k/f_4  [RC0402]  163.55 162.85 180 bottom
R423  ev@10k/f_4  [RC0402]  165.76 162.58 180 bottom
R424  ev@1.33k/f_4  [RC0402]  114.45 162.5 90 bottom
R425  *short_4  [SHORT0402]  167.34 161.87 90 bottom
R426  ev@10k/f_4  [RC0402]  163.6 161.61 180 bottom
R427  *ev@0_4  [RC0402]  165.69 161.49 0 bottom
R428  ev@1.33k/f_4  [RC0402]  113.95 160.72 0 bottom
R429  *ev@10k/f_4  [RC0402]  163.6 160.38 0 bottom
R430  ev@10k/f_4  [RC0402]  165.71 160.14 0 bottom
R431  ev@100k/f_4  [RC0402]  169.27 159.96 180 bottom
R432  *ev@40.2k/f_4  [RC0402]  163.6 159.09 0 bottom
R433  ev@10k/f_4  [RC0402]  163.61 157.98 180 bottom
R434  *short_4  [SHORT0402]  163.63 156.56 0 bottom
R435  evg@100k/f_4  [RC0402]  163.63 154.93 0 bottom
R436  evg@0_4  [RC0402]  163.63 153.89 180 bottom
R437  *ev@0_4  [RC0402]  163.4 150.82 270 bottom
R438  ev@10k/f_4  [RC0402]  113.28 150.06 0 bottom
R439  *ev@10k/f_4  [RC0402]  165.18 149.95 90 bottom
R440  ev@10k/f_4  [RC0402]  166.65 149.95 90 bottom
R441  *evg@0_4  [RC0402]  169.32 149.93 90 bottom
R442  ev@1.33k/f_4  [RC0402]  113.17 148.28 90 bottom
R443  ev@243/f_4  [RC0402]  127.66 148.25 90 bottom
R444  *ev@10k/f_4  [RC0402]  166.73 148.2 180 bottom
R445  *ev@0_4  [RC0402]  169.32 147.9 90 bottom
R446  *ev@10k/f_4  [RC0402]  163.1 147.06 90 bottom
R447  ev@1.33k/f_4  [RC0402]  113.95 146.5 0 bottom
R448  ev@10k/f_4  [RC0402]  152.73 141.5 90 bottom
R449  *ev@200/f_4  [RC0402]  139.42 141.47 180 bottom
R450  ev@2.49k/f_4  [RC0402]  137.72 141.42 270 bottom
R451  *ev@10k/f_4  [RC0402]  152.86 139.72 180 bottom
R452  100k_4  [RC0402]  119.31 129.48 180 bottom
R453  62_4  [RC0402]  98 127.2 90 bottom
R454  56_4  [RC0402]  99.17 127.2 90 bottom
R455  *short_4  [SHORT0402]  98.58 124.66 270 bottom
R456  *short_4  [SHORT0402]  99.85 124.66 90 bottom
R457  1k_4  [RC0402]  118.52 124.1 0 bottom
R458  *short_4  [SHORT0402]  95.36 123.84 0 bottom
R459  *100/f_4  [RC0402]  97.42 122.29 90 bottom
R460  100_4  [RC0402]  98.58 122.24 90 bottom
R461  100_4  [RC0402]  99.85 122.24 270 bottom
R462  *0_8  [RC0805]  102.26 122.24 0 bottom
R463  0_4  [RC0402]  118.55 122.24 90 bottom
R464  150/f_4  [RC0402]  163.36 120.68 90 bottom
R465  150/f_4  [RC0402]  164.5 120.68 90 bottom
R466  150/f_4  [RC0402]  165.64 120.68 90 bottom
R467  tpm@22_4  [RC0402]  173.49 119.5 0 bottom
R468  *0_8  [RC0805]  89.01 118.89 270 bottom
R469  8.2k_4  [RC0402]  149.44 118.62 270 bottom
R470  *short_4  [SHORT0402]  150.71 118.62 90 bottom
R471  7.5k/f_4  [RC0402]  151.72 118.62 90 bottom
R472  33_4  [RC0402]  168.05 118.52 90 bottom
R473  33_4  [RC0402]  169.07 118.52 90 bottom
R474  22_4  [RC0402]  171.12 118.48 90 bottom
R475  1m_4  [RC0402]  157.01 118.14 180 bottom
R476  10k_4  [RC0402]  172.14 117.98 90 bottom
R477  *short_8  [SHORT0805]  147.75 117.87 270 bottom
R478  *short_4  [SHORT0402]  173.41 117.75 90 bottom
R479  *0_4  [RC0402]  175.49 117.75 0 bottom
R480  *4.7k_4  [RC0402]  184.61 116.55 0 bottom
R481  *short_4  [SHORT0402]  189 115.89 180 bottom
R482  0.002/f_1206  [RC1206]  87.2 115.82 180 bottom
R483  *0_4  [RC0402]  177.93 115.79 180 bottom
R484  *short_4  [SHORT0402]  175.72 115.59 0 bottom
R485  *short_4  [SHORT0402]  87.86 113.94 180 bottom
R486  *short_4  [SHORT0402]  85.7 112.82 180 bottom
R487  *short_4  [SHORT0402]  88.96 112.69 0 bottom
R488  *short_8  [SHORT0805]  177.27 113.48 0 bottom
R489  0_8  [RC0805]  180.85 111.52 180 bottom
R490  49.9/f_4  [RC0402]  86.62 110.71 0 bottom
R491  *short_4  [SHORT0402]  88.92 110.65 0 bottom
R492  *4.7k_4  [RC0402]  189.69 110.43 0 bottom
R493  *short_6  [SHORT0603]  180.24 109.77 180 bottom
R494  10k_4  [RC0402]  141.91 109.44 270 bottom
R495  10k_4  [RC0402]  143.08 109.44 270 bottom
R496  10k_4  [RC0402]  144.25 109.44 270 bottom
R497  10k_4  [RC0402]  145.44 109.44 270 bottom
R498  33_4  [RC0402]  175.29 109.19 90 bottom
R499  *short_4  [SHORT0402]  147.73 109.12 0 bottom
R500  *short_4  [SHORT0402]  88.85 108.48 0 bottom
R501  *1k_4  [RC0402]  177.12 108.32 0 bottom
R502  *short_4  [SHORT0402]  86.72 108.02 0 bottom
R503  7.5k/f_4  [RC0402]  147.73 107.98 0 bottom
R504  *short_4  [SHORT0402]  88.88 107.26 0 bottom
R505  33_4  [RC0402]  177.07 107.21 0 bottom
R506  33_4  [RC0402]  178.74 106.83 90 bottom
R507  *10k_4  [RC0402]  183.87 106.6 180 bottom
R508  tpm@10k_4  [RC0402]  186.01 106.6 180 bottom
R509  *10k_4  [RC0402]  181.71 106.47 0 bottom
R510  10k_4  [RC0402]  59.95 106.19 270 bottom
R511  *short_4  [SHORT0402]  88.88 106.19 0 bottom
R512  *short_8  [SHORT0805]  140.77 106.14 90 bottom
R513  *10k_4  [RC0402]  61.75 105.38 0 bottom
R514  *10k_4  [RC0402]  181.71 105.35 0 bottom
R515  10k_4  [RC0402]  183.77 105.25 180 bottom
R516  *short_4  [SHORT0402]  88.85 105.02 0 bottom
R517  10k_4  [RC0402]  179.91 104.23 180 bottom
R518  *0_4  [RC0402]  177.7 104.21 0 bottom
R519  *10k_4  [RC0402]  183.09 104.08 180 bottom
R520  75_4  [RC0402]  86.97 103.23 270 bottom
R521  43_4  [RC0402]  88.14 103.22 270 bottom
